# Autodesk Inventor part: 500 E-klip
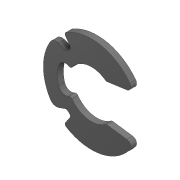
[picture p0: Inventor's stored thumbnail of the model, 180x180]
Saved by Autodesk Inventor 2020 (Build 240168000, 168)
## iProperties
Created: 2020-01
Part Number: 500 E-klip
Material: Steel, High Strength, Low Alloy
Document SubType Name: Modeling
Designer: woodk
Density: 7.85 g/cm^3
Appearance: Steel - Polished
Vendor: KoP
Mass: 1.82564 g
Surface Area: 4.92768 cm^2
Volume: 0.232566 cm^3
Author: woodk
Revision Number: ANY
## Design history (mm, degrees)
feature "Imported1"
body "Solid1"
